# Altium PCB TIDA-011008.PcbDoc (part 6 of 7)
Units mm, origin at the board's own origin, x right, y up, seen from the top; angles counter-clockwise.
Board outline 252 x 205 mm, 4 copper layers (Top Layer, Inner Layer 1, Inner Layer 2, Bottom Layer), stack 1.926 mm thick; 517 components, 293 nets, 1426 pads, 1855 vias.
Unrouted connection lines stored in the file: 4.
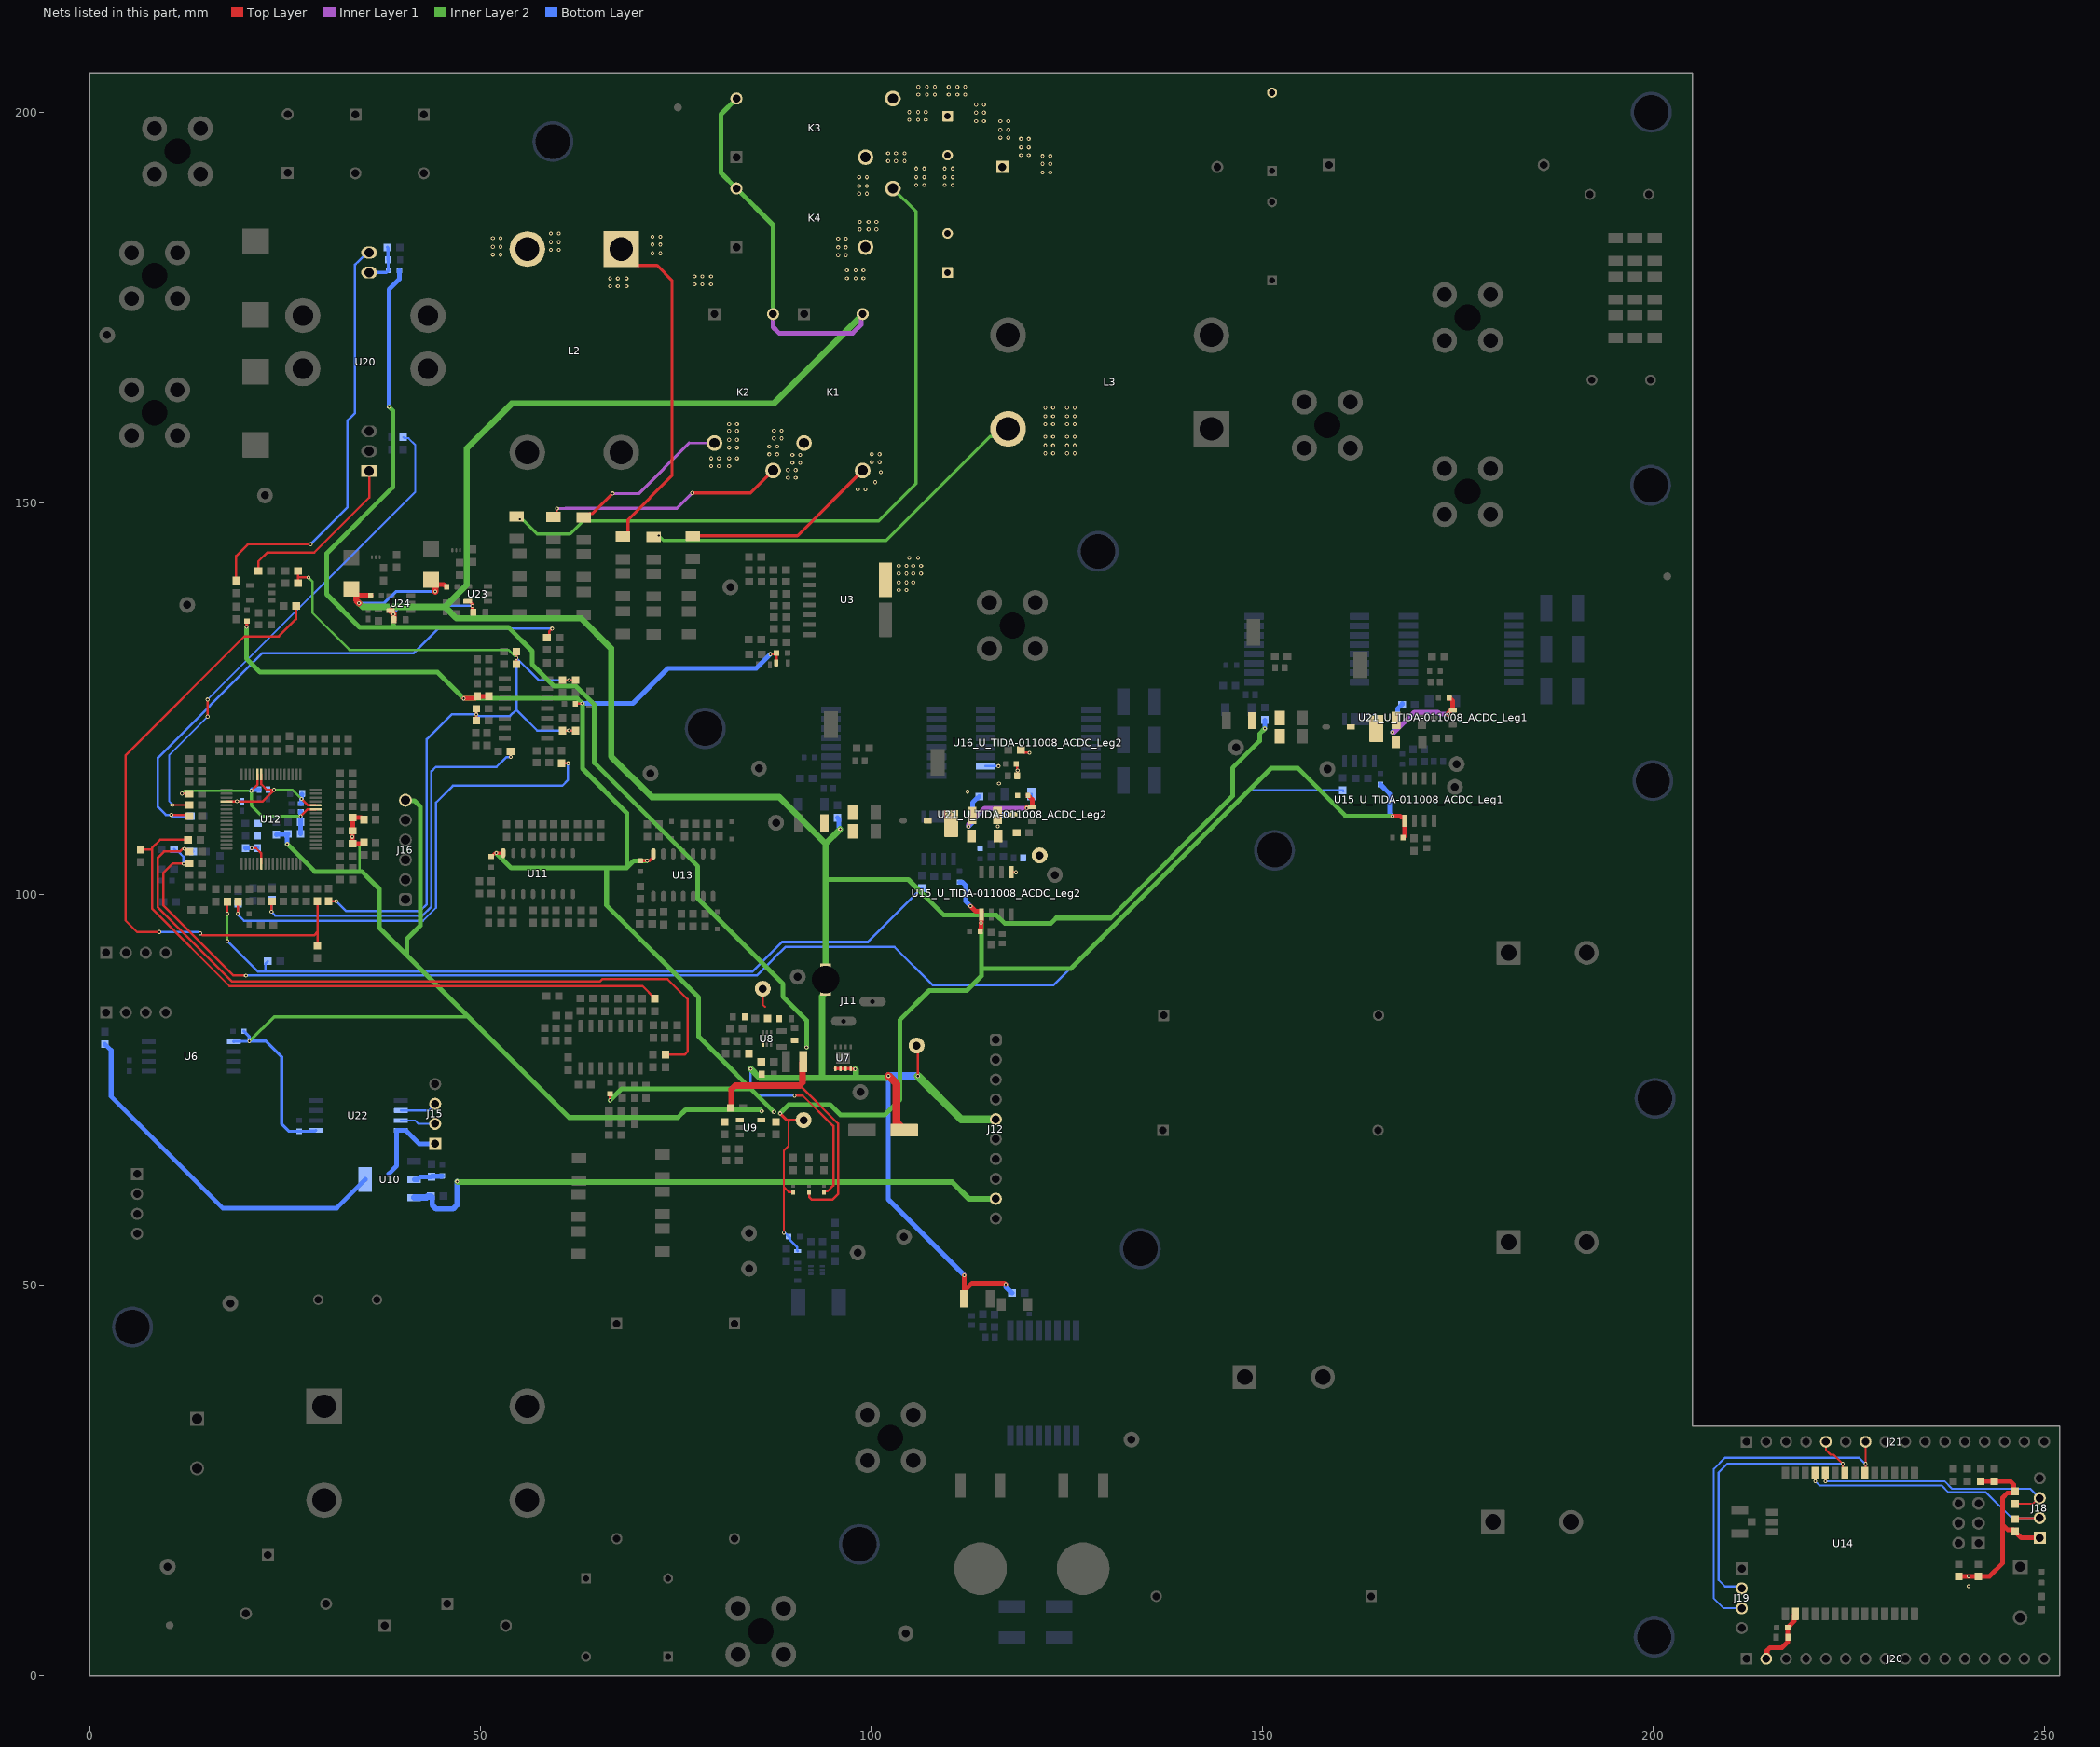
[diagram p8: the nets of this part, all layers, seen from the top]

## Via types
v1: diameter 0.508, hole 0.254, Top Layer to Bottom Layer, tented both sides, 1852 vias
v2: diameter 1.5/1.5/1.5/1.5 (per signal layer), hole 1, Top Layer to Bottom Layer, 2 vias
v3: diameter 0.508, hole 0.254, Top Layer to Bottom Layer, 1 vias

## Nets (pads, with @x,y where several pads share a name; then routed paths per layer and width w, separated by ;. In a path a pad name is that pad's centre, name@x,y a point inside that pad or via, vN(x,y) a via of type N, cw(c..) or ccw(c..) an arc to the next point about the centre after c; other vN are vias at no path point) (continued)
SN_U_TIDA-011008_ACDC_Leg2: C19_U_TIDA-011008_ACDC_Leg2.2 C109_U_TIDA-011008_ACDC_Leg2.1 C110_U_TIDA-011008_ACDC_Leg2.2 C111_U_TIDA-011008_ACDC_Leg2.2 C112_U_TIDA-011008_ACDC_Leg2.2 C113_U_TIDA-011008_ACDC_Leg2.1 C114_U_TIDA-011008_ACDC_Leg2.1 C115_U_TIDA-011008_ACDC_Leg2.1 C117_U_TIDA-011008_ACDC_Leg2.1 D14_U_TIDA-011008_ACDC_Leg2.2 R177_U_TIDA-011008_ACDC_Leg2.1 TP28_U_TIDA-011008_ACDC_Leg2.1 U15_U_TIDA-011008_ACDC_Leg2.5 U16_U_TIDA-011008_ACDC_Leg2.10 U21_U_TIDA-011008_ACDC_Leg2.3 | length 6.3
  Top Layer w0.3: U15_U_TIDA-011008_ACDC_Leg2.5@117.897,102.808 v1(118.495,102.808) v1@118.53,102.773 ; C113_U_TIDA-011008_ACDC_Leg2.1@118.53,116.65 118.664,116.515 118.664,115.847 v1(118.704,115.807) ; C115_U_TIDA-011008_ACDC_Leg2.1@118.642,115.158 118.705,115.221 v1(118.704,115.807) ; R177_U_TIDA-011008_ACDC_Leg2.1@119.115,118.44 119.44,118.115 120.2,118.115 v1@120.238,118.077
  Top Layer w0.8: C111_U_TIDA-011008_ACDC_Leg2.2@116.163,107.608 C111_U_TIDA-011008_ACDC_Leg2.2@116.2,107.571
  Bottom Layer w0.3: U16_U_TIDA-011008_ACDC_Leg2.10@114.605,116.376 116.252,116.376 v1(116.255,116.373) ; C112_U_TIDA-011008_ACDC_Leg2.2@120.493,112.577 C112_U_TIDA-011008_ACDC_Leg2.2@120.493,112.827
  Bottom Layer w0.8: D14_U_TIDA-011008_ACDC_Leg2.2@116.235,110.254 116.235,110.199 116.293,110.141 v1(116.988,110.141)
  other v1: 116.163,108.667 112.288,113.117 116.316,114.155 120.219,118.096
SWCLK: J19.3 J21.7 U14.20 | length 45.1
  Top Layer w0.254: U14.20@227.07,25.975 227.16,26.065 v1(227.16,27.156) J21.7@227.16,29.975
  Bottom Layer w0.254: J19.3@211.32,8.685 209.003,8.685 207.75,9.938 207.75,26.507 209.16,27.917 226.336,27.917 227.098,27.156 v1(227.16,27.156) ; J21.7@227.114,29.929 J21.7@227.16,29.975
SWDIO: J19.2 J21.5 U14.22 | length 38.7
  Top Layer w0.254: J21.5@222.08,29.975 222.08,28.92 222.693,28.307 223.086,28.307 v1(224.237,27.156) 224.237,26.268 U14.22@224.53,25.975
  Bottom Layer w0.254: J19.2@211.32,11.225 211.072,11.473 209.188,11.473 208.357,12.304 208.357,26.052 209.461,27.156 v1(224.237,27.156)
TEMP_SW1: C120_U_TIDA-011008_ACDC_Leg1.1 R135.2 R178_U_TIDA-011008_ACDC_Leg1.1 | length 179.1
  Top Layer w0.3: R135.2@12.79,103.965 12.727,103.902 v1(12.04,103.902) 10.625,103.902 9.426,102.703 9.426,98.569 18.393,89.601 v1(20,89.601)
  Bottom Layer w0.3: C120_U_TIDA-011008_ACDC_Leg1.1@10.824,105.749 11.149,105.424 11.375,105.424 12.001,104.799 12.001,103.942 v1(12.04,103.902) ; v1(20,89.601) 85.371,89.601 87.52,91.75 87.52,91.775 88.995,93.25 102.968,93.25 107.869,88.349 123.266,88.349 148.187,113.27 R178_U_TIDA-011008_ACDC_Leg1.1@160.298,113.27 R178_U_TIDA-011008_ACDC_Leg1.1@160.373,113.195
TEMP_SW2: C120_U_TIDA-011008_ACDC_Leg2.1 R136.2 R178_U_TIDA-011008_ACDC_Leg2.1 | length 101.5
  Top Layer w0.3: v1(17.628,97.5) R136.2@17.628,99.056
  Inner Layer 2 w0.3: v1(17.628,94) v1(17.628,97.5)
  Bottom Layer w0.3: v1(17.628,94) 21.525,90.103 22.472,90.103 ; C120_U_TIDA-011008_ACDC_Leg2.1@22.799,91.421 22.797,91.421 22.472,91.096 22.472,90.103 ; R178_U_TIDA-011008_ACDC_Leg2.1@106.53,100.699 R178_U_TIDA-011008_ACDC_Leg2.1@106.455,100.774 106.455,100.749 106.13,100.424 106.105,100.424 99.564,93.883 88.593,93.883 84.813,90.103 22.472,90.103
UART1_RX: J15.3 J18.3 R167.1 U14.24 U22.6 | length 38
  Top Layer w0.254: U14.24@221.99,25.975 222.042,25.923 v1(222.042,24.926) ; R167.1@245.995,21.75 R167.1@246.285,22.04 248.53,22.04 249.255,22.765 J18.3@249.44,22.765
  Bottom Layer w0.254: U22.6@39.83,72.335 43.357,72.335 J15.3@44.202,73.18 ; v1(222.042,24.926) 237.268,24.926 238.242,23.952 248.253,23.952 J18.3@249.44,22.765
UART1_TX: J15.2 J18.2 R168.1 U14.25 U22.7 | length 39.5
  Top Layer w0.254: v1(220.715,24.931) 220.715,25.97 U14.25@220.72,25.975 ; R168.1@246.285,20.065 R168.1@246.285,20.09 246.42,20.225 J18.2@249.44,20.225
  Bottom Layer w0.254: U22.7@39.83,71.065 41.621,71.065 42.046,70.64 J15.2@44.202,70.64 ; v1(220.715,24.931) 221.255,24.39 236.875,24.39 237.747,23.518 242.543,23.518 245.836,20.225 J18.2@249.44,20.225
V_ZCD: C132.2 R195.2 R200.2 | length 83
  Top Layer w0.3: v1(8.945,95.162) 6.083,95.162 4.59,96.655 4.59,117.749 19.807,132.967 24.2,132.967 26.408,135.175 R195.2@26.408,136.855 ; v1(14.178,94.987) 14.207,94.987 14.454,94.741 28.706,94.741 29.145,95.179 ; C132.2@29.145,93.437 29.145,95.179 ; R200.2@29.145,99.081 29.145,95.179
  Bottom Layer w0.3: v1(8.945,95.162) 13.947,95.162 14.122,94.987 v1(14.178,94.987)
VAC_input: C53.2 R67.2 R138.2 | length 63.9
  Top Layer w0.3: v1(18.967,97.5) 18.967,98.994 R138.2@19.029,99.056 ; R67.2@60.376,116.739 60.383,116.731 v1(61.204,116.731)
  Bottom Layer w0.3: C53.2@19.029,98.824 18.967,98.763 v1(18.967,97.5) 18.967,97.398 19.767,96.599 42.641,96.599 44.311,98.269 44.311,111.714 46.472,113.875 60.466,113.875 61.204,114.614 v1(61.204,116.731)
VAC_L: K2.2 L2.2 R58.1 | length 20.6
  Top Layer w0.4: R58.1@63.221,148.35 63.621,148.35 63.944,148.673 64.325,148.673 v1(66.895,151.243)
  Inner Layer 1 w0.254: 76.691,157.691 K2.2@79.93,157.691
  Inner Layer 1 w0.4: v1(66.895,151.243) 66.913,151.225 68.428,151.225 68.433,151.22 70.22,151.22 76.691,157.691
  other v1: 79.5,154.739 80.495,154.739 81.808,154.739 79.5,155.739 80.495,155.739 81.808,155.739 82.804,155.739 81.808,157.114 82.804,157.114 81.808,158.114 82.804,158.114 81.808,159.25 82.804,159.25 81.808,160.096 82.804,160.096 51.58,181.79 52.576,181.79 59.014,182.392 60.01,182.392 51.58,182.79 52.576,182.79 59.014,183.392 60.01,183.392 51.58,183.898 52.576,183.898 59.014,184.5 60.01,184.5
VAC_L_Relay: K1.2 K2.3 R12.2 R61.1 | length 30.9
  Top Layer w0.254: R61.1@59.34,148.403 59.522,148.403 59.845,148.726 59.793,148.726 v1(59.793,149.327)
  Top Layer w0.4: v1(77.1,151.325) 84.564,151.325 K2.3@87.43,154.191
  Inner Layer 1 w0.4: v1(59.793,149.327) 60.821,149.327 60.847,149.354 75.128,149.354 v1(77.1,151.325)
  other v1: 89.32,153.245 90.316,153.245 89.32,154.245 90.316,154.245 89.897,155.164 90.893,155.164 89.897,156.164 90.893,156.164 86.945,156.256 87.94,156.256 86.945,157.256 87.94,157.256 87.527,158.289 88.522,158.289 87.527,159.289 88.522,159.289
VAC_L_SW: K1.3 R12.1 R64.1 U3.2 | length 25.2
  Top Layer w0.4: R64.1@77.153,145.85 90.541,145.85 K1.3@98.882,154.191
  other v1: 103.5,138.876 104.495,138.876 103.5,139.876 104.495,139.876 105.356,139.876 103.5,141 104.495,141 105.356,141 106.351,141 103.5,142 104.495,142 105.356,142 106.351,142 104.85,143.015 105.974,143.015 98.25,151.754 99.245,151.754 100.503,152.694 101.198,153.975 100.054,155.257 101.049,155.257 100.054,156.257 101.049,156.257
VAC_N: K4.2 L2.1 R70.1 | length 43.6
  Top Layer w0.254: L2.1@68,182.5 L2.1@70.103,180.397 ; R70.1@68.201,145.871 68.551,145.871 R70.1@68.874,146.194
  Top Layer w0.4: R70.1@68.874,146.194 68.874,147.874 74.5,153.5 74.5,178.5 72.603,180.397 L2.1@70.103,180.397
  other v1: 66.568,177.755 67.568,177.755 68.676,177.755 77.381,178.006 78.381,178.006 79.489,178.006 66.568,178.75 67.568,178.75 68.676,178.75 96.875,178.773 97.983,178.773 98.983,178.773 77.381,179.002 78.381,179.002 79.489,179.002 96.875,179.768 97.983,179.768 98.983,179.768 95.75,181.718 96.745,181.718 72.005,181.97 73,181.97 95.75,182.718 96.745,182.718 72.005,183.078 73,183.078 95.75,183.826 96.745,183.826 72.005,184.078 73,184.078 98.533,184.99 99.641,184.99 100.641,184.99 98.533,185.985 99.641,185.985 100.641,185.985
VAC_N_Relay: K3.2 K4.3 R25.2 R73.1 | length 93.8
  Top Layer w0.4: R73.1@54.595,148.477 54.719,148.477 55.042,148.154 v1(55.042,147.941)
  Inner Layer 2 w0.4: v1(55.042,147.941) 55.373,147.941 57.241,146.073 61.457,146.073 62.912,147.529 63.142,147.758 100.934,147.758 105.694,152.519 105.694,187.306 K4.3@102.75,190.25
  other v1: 98.429,189.58 99.425,189.58 98.429,190.58 99.425,190.58 105.75,190.688 106.745,190.688 109.386,190.688 110.381,190.688 98.429,191.688 99.425,191.688 105.75,191.688 106.745,191.688 109.386,191.688 110.381,191.688 105.75,192.796 106.745,192.796 109.386,192.796 110.381,192.796 102.142,193.755 103.142,193.755 104.25,193.755 102.142,194.75 103.142,194.75 104.25,194.75
VAC_N_SW: C27.1 C30.2 K3.3 L3.4 R25.1 R76.1 | length 51.5
  Top Layer w0.4: R76.1@72.136,145.843 v1(72.806,145.843)
  Inner Layer 2 w0.4: v1(72.806,145.843) 72.822,145.843 73.415,145.25 101.906,145.25 115.195,158.539 115.416,158.539 116.377,159.5 L3.4@117.5,159.5
  other v1: 122.25,156.387 123.245,156.387 125.017,156.387 126.012,156.387 122.25,157.387 123.245,157.387 125.017,157.387 126.012,157.387 122.25,158.495 123.245,158.495 125.017,158.495 126.012,158.495 122.25,160.123 123.245,160.123 125.017,160.123 126.012,160.123 122.25,161.123 123.245,161.123 125.017,161.123 126.012,161.123 122.25,162.231 123.245,162.231 125.017,162.231 126.012,162.231 121.882,192.292 122.878,192.292 121.882,193.401 122.878,193.401 121.882,194.401 122.878,194.401 119.13,194.5 120.125,194.5 119.13,195.5 120.125,195.5 119.13,196.608 120.125,196.608 116.505,196.75 117.5,196.75 116.505,197.75 117.5,197.75 113.405,198.858 114.4,198.858 116.505,198.858 117.5,198.858 104.855,199.031 105.963,199.031 106.963,199.031 113.405,199.966 114.4,199.966 104.855,200.026 105.963,200.026 106.963,200.026 113.405,200.966 114.4,200.966 106.006,202.25 107.114,202.25 108.114,202.25 109.892,202.25 111,202.25 112,202.25 106.006,203.245 107.114,203.245 108.114,203.245 109.892,203.245 111,203.245 112,203.245
VAC_relay: C54.2 R68.2 R148.2 | length 72.1
  Top Layer w0.3: v1(10.45,110.14) 12.615,110.14 R148.2@12.79,109.965 ; R68.2@58.495,132.827 58.768,133.1 58.768,133.565 v1(59.162,133.959)
  Bottom Layer w0.3: C54.2@12.974,109.965 10.681,109.965 10.506,110.14 v1(10.45,110.14) 9.758,110.14 8.75,111.148 8.75,117.447 22.125,130.823 41.454,130.823 44.625,133.993 59.128,133.993 v1(59.162,133.959)
VAC_sw: C55.2 R69.2 R139.2 | length 53
  Top Layer w0.3: v1(23.265,97.75) 23.265,98.989 R139.2@23.348,99.072 ; R69.2@53.868,118.263 53.868,117.55 v1@53.88,117.538
  Bottom Layer w0.3: C55.2@23.348,99.299 23.265,99.216 v1(23.265,97.75) 23.761,97.254 42.56,97.254 43.733,98.427 43.733,115.707 44.289,116.264 52.043,116.264 53.318,117.538 v1(53.868,117.538)
VCC_1V2: C92.2 C93.2 C94.2 C95.2 U12.4 U12.44 U12.59 | length 18.8
  Top Layer w0.3: U12.4@17.515,111.852 18.829,111.852 v1(18.849,111.872) 18.878,111.843 22.103,111.843 v1(23.6,113.34) 22.687,113.34 21.965,114.062 U12.59@21.965,115.302 ; v1(27.115,112.177) 27.94,111.352 U12.44@28.915,111.352
  Inner Layer 2 w0.3: v1(23.6,113.34) 23.634,113.375 25.918,113.375 v1(27.115,112.177)
  Bottom Layer w0.3: v1(18.849,111.872) 18.852,111.875 19.501,111.875 C93.2@19.504,111.877 ; C92.2@22.84,113.377 22.859,113.359 23.582,113.359 v1(23.6,113.34)
  Bottom Layer w0.6: C94.2@27.015,111.577 27.115,111.577 v1(27.115,112.177) 27.115,112.702 C95.2@27.19,112.777
VCC_1V65: C48.2 C50.2 C51.2 C52.2 C131.2 R49.2 R55.2 R56.2 R57.2 R197.1 R202.2 | length 112.1
  Top Layer w0.3: 26.665,140.282 26.665,140.5 ; C131.2@26.665,141.307 26.665,140.532 26.697,140.5 v1(28,140.5) ; R202.2@30.593,99.097 30.596,99.094 v1(31.563,99.094) ; R57.2@49.467,122.192 v1(49.467,122.992) C52.2@49.467,123.717 ; R49.2@54.593,129.397 v1(54.593,130.22) C48.2@54.593,131.043 ; R55.2@60.476,120.94 v1(61.308,120.94) 62.141,120.94 C50.2@62.154,120.926 ; R56.2@60.476,127.38 v1(61.315,127.38) C51.2@62.154,127.38
  Inner Layer 2 w0.3: v1(28,140.5) 28.5,140 28.5,136 33.25,131.25 53.563,131.25 v1(54.593,130.22)
  Bottom Layer w0.3: v1(31.563,99.094) 32.801,97.857 42.271,97.857 43.136,98.721 43.136,119.819 46.308,122.992 49.52,122.992 49.743,122.77 53.77,122.77 54.593,123.593 ; v1(61.308,120.94) 57.246,120.94 54.593,123.593 ; v1(61.315,127.38) 57.433,127.38 v1(54.593,130.22) 54.593,123.593
VCC_3V3: C43.2 C65.1 C67.1 C72.2 C84.2 C89.2 C97.1 C103.1 C108_U_TIDA-011008_ACDC_Leg1.2 C108_U_TIDA-011008_ACDC_Leg2.2 D8.2 FB1.1 FB4.1 FB5.2 FB6.1 FB7_U_TIDA-011008_ACDC_Leg1.1 FB7_U_TIDA-011008_ACDC_Leg2.1 FB8.1 J16.6 L7.1 L8.1 R9.2 R35.2 R38.1 R155.2 R156.2 R157.2 R190.2 R191.2 TP20.1 U6.1 U9.5 U11.16 U13.14 U15_U_TIDA-011008_ACDC_Leg1.1 U15_U_TIDA-011008_ACDC_Leg2.1 U22.1 | length 508.1
  Top Layer w0.254: v1(88.8,56.717) 88.8,62.54 ; 89.6,71.108 89.425,70.933 89.425,67.84 88.8,67.215 88.8,62.54 ; D8.2@90.012,61.9 89.44,61.9 88.8,62.54
  Top Layer w0.3: FB6.1@62.127,124.332 62.165,124.37 62.978,124.37 v1(63.016,124.407) ; v1(87.081,130.685) 87.7,130.685 FB4.1@87.87,130.855 87.87,129.635 R35.2@87.82,129.585
  Top Layer w0.4: v1(20.083,134.171) 20.104,134.192 20.104,134.895 FB8.1@20.132,134.923 ; C84.2@51.368,104.81 51.393,104.81 51.568,104.985 51.568,105.01 51.818,105.26 v1(52.021,105.26) U11.16@52.923,105.26 ; v1(66.579,73.64) FB5.2@66.579,74.477 ; C89.2@70.432,104.281 v1(71.307,104.281) 71.618,104.281 72.122,104.785 U13.14@72.122,105.156 ; v1(88.325,71.968) 89.184,71.108 89.6,71.108 TP20.1@91.33,71.108
  Top Layer w0.6: R191.2@35.088,106.577 34.938,106.577 34.823,106.462 R157.2@33.647,106.462 33.624,106.484 v1(33.624,107.337) 33.624,108.068 R155.2@33.659,108.102 33.652,108.109 33.652,109.801 R156.2@33.645,109.808 34.732,109.808 34.938,109.602 R190.2@35.088,109.602 ; v1(47.856,125.034) C43.2@49.318,125.034 ; C43.2@49.598,125.314 R38.1@51.098,125.314 ; v1(112.68,98.471) 113.356,97.795 114.087,97.795 U15_U_TIDA-011008_ACDC_Leg2.1@114.087,97.408 114.087,96.382 v1(114.031,96.325) 114.031,95.676 113.942,95.588 113.942,95.258 C108_U_TIDA-011008_ACDC_Leg2.2@113.917,95.233 ; v1(166.662,109.976) 167.61,109.976 167.707,109.879 168.182,109.879 U15_U_TIDA-011008_ACDC_Leg1.1@168.182,109.404 168.182,107.424 168.012,107.254 C108_U_TIDA-011008_ACDC_Leg1.2@168.012,107.229
  Inner Layer 2 w0.3: v1(33.624,107.337) 33.658,107.303 33.658,106.981 34.517,106.123 34.517,102.899
  Inner Layer 2 w0.4: v1(20.438,81.212) 20.467,81.212 20.521,81.266 20.532,81.266 23.6,84.334 48.439,84.334
  Inner Layer 2 w0.6: v1(20.083,134.171) 20.083,130.111 21.818,128.376 44.514,128.376 v1(47.856,125.034) 62.389,125.034 v1(63.016,124.407) ; v1(25.286,106.418) 28.804,102.899 34.517,102.899 34.82,102.899 35.863,101.856 35.881,101.856 37.063,100.673 37.063,95.709 40.595,92.177 ; J16.6@40.399,112.017 40.482,111.934 41.556,111.934 42.306,111.184 42.306,95.982 40.595,94.272 40.595,92.177 ; v1(52.021,105.26) 53.916,103.364 66.128,103.364 ; v1@63.048,124.375 63.048,116.049 68.702,110.395 68.702,103.364 ; v1(66.579,73.64) 68.04,75.101 84.344,75.101 ; v1@71.303,104.276 69.614,104.276 68.702,103.364 ; v1(85.966,72.257) 85.81,72.413 76.229,72.413 75.258,71.442 61.33,71.442 48.439,84.334 40.595,92.177 ; v1(87.537,72.161) 77.915,81.784 77.915,86.783 66.128,98.569 66.128,103.364 ; v1(88.325,71.968) 89.425,73.068 94.728,73.068 96.039,71.757 101.701,71.757 103.676,73.732 103.676,83.948 107.412,87.684 112.208,87.684 114.087,89.563 114.087,90.5 ; v1(114.031,96.325) 114.087,96.269 114.087,90.5 ; v1@166.636,110.002 160.661,110.002 154.528,116.135 151.167,116.135 125.532,90.5 114.087,90.5 ; 66.128,103.364 68.702,103.364
  Bottom Layer w0.3: v1(88.8,56.717) 88.924,56.717 FB1.1@89.425,56.215 89.625,56.015 89.625,55.743 90.485,54.883 90.485,54.448 R9.2@90.575,54.359
  Bottom Layer w0.4: U6.1@18.46,81.155 18.497,81.191 20.417,81.191 v1(20.438,81.212) ; C65.1@19.748,82.475 20.417,81.805 20.417,81.233 v1(20.438,81.212) ; U22.1@28.93,69.795 28.83,69.695 28.23,69.695 28.214,69.679 C67.1@26.822,69.679 25.505,69.679 24.575,70.61 24.575,79.174 22.536,81.212 v1(20.438,81.212)
  Bottom Layer w0.6: C103.1@23.895,107.615 23.933,107.653 L8.1@25.353,107.653 ; v1(25.286,106.418) 25.286,107.586 L8.1@25.353,107.653 ; L8.1@25.39,107.69 L8.1@25.353,107.653 ; v1(63.016,124.407) 63.024,124.399 69.504,124.399 73.972,128.866 85.261,128.866 v1(87.081,130.685) ; FB7_U_TIDA-011008_ACDC_Leg2.1@111.26,101.54 111.31,101.49 111.702,101.49 112.054,101.139 112.054,99.097 v1(112.68,98.471) ; FB7_U_TIDA-011008_ACDC_Leg1.1@165.104,114.036 166.275,112.865 166.275,110.363 v1(166.662,109.976)
VCC_3V3_Wifi: C68.2 C74.2 C105.2 C106.2 J15.1 J18.1 J20.2 L6.1 R162.2 R163.2 R167.2 R168.2 R169.2 R170.2 U10.2 U10.4 U14.2 U22.8 | length 97.9
  Top Layer w0.6: J20.2@214.46,2.225 214.557,2.322 214.557,3.261 214.929,3.633 216.462,3.633 217.2,4.371 217.2,4.925 C105.2@217.275,5 217.2,5.075 C106.2@217.2,6.207 218.03,7.037 218.03,7.825 U14.2@218.112,7.908 ; R163.2@239.085,12.75 R162.2@241.605,12.75 243.005,12.75 244.702,14.447 244.702,19.355 ; R169.2@241.865,24.918 245.675,24.918 246.11,24.483 246.11,23.815 R167.2@246.285,23.64 246.285,23.615 246.11,23.44 245.313,23.44 244.702,22.829 244.702,19.355 ; R168.2@246.285,18.465 247.065,17.685 J18.1@249.44,17.685 ; R168.2@246.285,18.49 246.285,18.515 246.11,18.69 245.367,18.69 244.702,19.355
  Bottom Layer w0.6: L6.1@1.961,80.831 1.961,80.806 2.136,80.631 2.161,80.631 2.761,80.031 2.761,74.126 17.017,59.87 31.617,59.87 U10.4@35.262,63.514 ; 38.275,64.245 39.29,65.26 39.29,69.795 40.43,69.795 42.125,68.1 J15.1@44.202,68.1 ; U10.2@41.512,63.514 41.937,63.514 42.281,63.858 C74.2@43.727,63.858 43.8,63.931 45.063,63.931 C68.2@45.113,63.981
  other v1: 240.345,11.512 240.345,12.75
VCC_5V: C71.2 C76.1 C79.1 C80.1 C138.2 C139.2 D7.2 FB9.2 L5.2 R101.2 R103.2 TP22.1 U9.1 U23.5 U24.5 | length 195.4
  Top Layer w0.254: TP22.1@86.108,87.915 86.108,85.876 86.39,85.594
  Top Layer w0.3: 90.877,75.518 95.726,70.669 95.726,61.657 95.005,60.936 92.405,60.936 92.041,61.301 92.041,61.892 D7.2@92.033,61.9
  Top Layer w0.4: U23.5@48.365,137.443 48.615,137.443 48.959,137.098 v1(48.959,136.876) 48.959,136.183 C139.2@49.095,136.048
  Top Layer w0.8: U24.5@38.501,136.252 38.551,136.252 38.876,135.926 v1(38.876,135.776) 38.876,135.088 C138.2@38.874,135.086 ; C71.2@82.008,72.658 82.033,72.658 82.108,72.733 82.108,73.168 82.109,73.169 82.109,75.049 82.578,75.518 90.877,75.518 ; 90.837,75.558 91.187,75.907 91.187,78.512 L5.2@91.283,78.608
  Inner Layer 2 w0.6: v1(38.298,162.329) 38.773,161.854 38.773,152.023 30.324,143.574 30.324,138.349 34.55,134.123 39.146,134.123 ; 38.876,134.104 39.164,134.104 ; v1(38.876,135.776) 38.876,134.392 39.164,134.104 ; v3(91.708,80.409) 91.708,83.866 88.682,86.891 88.682,88.537 77.799,99.421 77.799,103.559 64.569,116.79 64.569,124.247 62.223,126.593 59.421,126.593 56.63,129.385 56.63,131.071 53.596,134.104 39.164,134.104
  Bottom Layer w0.3: v1(38.876,135.776) 38.916,135.815 38.916,135.992 39.801,136.876 v1(48.959,136.876)
  Bottom Layer w0.6: v1(38.298,162.329) 38.298,177.344 39.623,178.669 FB9.2@39.623,179.756
VCC_5V_WiFi: C73.2 J12.9 U10.3 | length 79.9
  Inner Layer 2 w0.7: v1(47.003,63.264) 47.085,63.182 110.318,63.182 112.448,61.052 J12.9@115.917,61.052
  Bottom Layer w0.7: C73.2@43.602,61.333 43.777,61.333 43.827,61.283 43.827,60.247 44.324,59.75 46.5,59.75 47.003,60.253 v1(47.003,63.264)
  Bottom Layer w0.8: U10.3@41.512,61.214 41.525,61.228 43.108,61.228 43.213,61.333 C73.2@43.602,61.333
VCC_12V: C9.1 C28.2 C29.2 C69.1 C75.1 C77.2 C123_U_TIDA-011008_ACDC_Leg1.1 C123_U_TIDA-011008_ACDC_Leg2.1 D2.1 D3.1 D6.2 J11.1 J12.5 K1.4 K2.4 K3.4 K4.4 R1.1 R102.2 R171_U_TIDA-011008_ACDC_Leg1.1 R171_U_TIDA-011008_ACDC_Leg2.1 R172_U_TIDA-011008_ACDC_Leg1.1 R172_U_TIDA-011008_ACDC_Leg2.1 R179_U_TIDA-011008_ACDC_Leg1.1 R179_U_TIDA-011008_ACDC_Leg2.1 TP7.1 U7.1 U7.2 U7.3 U7.4 U8.1 | length 445.9
  Top Layer w0.3: v1(90.183,74.243) 91.226,74.243 95.131,70.338 95.131,62.761 94.382,62.012 94.033,62.012 93.933,61.912 D6.2@93.933,61.9 ; TP7.1@105.793,80.646 105.951,80.488 v1(105.951,76.743)
  Top Layer w0.4: U7.1@95.408,77.679 U7.2@96.058,77.679 U7.3@96.708,77.679 U7.4@97.358,77.679 97.399,77.638 v1(97.908,77.638)
  Top Layer w0.6: D3.1@34.1,138.425 34.322,138.203 C28.2@35.97,138.203 ; D2.1@44.588,139.62 45.289,139.62 45.552,139.356 45.64,139.356 45.665,139.331 C29.2@45.665,139.306 ; C9.1@111.875,48.275 112,48.4 112,49.374 112.892,50.266 117.027,50.266 v1(117.191,50.101) ; C9.1@111.875,48.825 v1(111.875,51.262)
  Top Layer w0.8: D3.1@33.5,139.025 34.1,138.425 34.1,137.592 v1(34.467,137.226) ; D2.1@43.694,140.193 44.214,139.673 v1(44.214,138.704)
  Top Layer w1: v1(102.199,76.761) 103.211,75.749 103.211,70.803 ; C69.1@103.211,70.112 103.211,70.803 ; C69.1@103.511,69.812 C69.1@104.201,69.812 103.211,70.803
  Inner Layer 1 w0.6: K2.4@87.43,174.191 87.434,174.188 87.434,172.516 88.2,171.75 97.612,171.75 98.7,172.838 98.7,174.01 K1.4@98.882,174.191
  Inner Layer 2 w0.6: K3.4@82.75,201.75 80.75,199.75 80.75,192.25 K4.4@82.75,190.25 87.43,185.57 K2.4@87.43,174.191 ; 94.149,101.876 104.721,101.876 109.27,97.328 116.002,97.328 117.037,96.293 122.981,96.293 123.64,96.952 130.612,96.952 146.193,112.533 146.193,116.141 149.646,119.594 149.646,120.507 v1(150.317,121.178)
  Inner Layer 2 w0.8: v1(34.467,137.226) 34.948,136.744 45.463,136.744 ; v1(84.558,77.681) 85.742,76.497 93.829,76.497 ; v1(96,108.321) 94.149,106.469 ; v1(97.908,77.638) 98.033,77.513 98.033,76.497 ; K1.4@98.882,174.127 87.505,162.75 54,162.75 48.25,157 48.25,139.531 45.463,136.744 ; v1@102.164,76.743 101.917,76.497 98.033,76.497 ; 45.463,136.744 46.923,135.284 62.877,135.284 66.716,131.445 66.716,117.622 71.925,112.413 88.205,112.413 94.149,106.469 ; 93.829,76.497 98.033,76.497 ; 93.829,76.497 93.699,76.627 93.699,86.947 93.849,87.097 93.849,88.765 J11.1@94.149,89.065 94.149,101.876 94.149,106.469
  Inner Layer 2 w1: v1(105.951,76.743) 111.481,71.212 J12.5@115.917,71.212
  Bottom Layer w0.3: v1(84.558,77.681) 84.558,75.141 85.456,74.243 v1(90.183,74.243)
  Bottom Layer w0.4: v1(34.467,137.226) 37.718,137.226 39.197,138.704 v1(44.214,138.704)
  Bottom Layer w0.6: R179_U_TIDA-011008_ACDC_Leg2.1@95.648,109.79 95.823,109.615 95.823,108.498 v1(96,108.321) ; v1@102.164,76.743 102.164,60.974 v1(111.875,51.262) ; v1(117.191,50.101) 117.191,49.774 117.965,49 R1.1@117.99,49 ; v1(150.317,121.178) R179_U_TIDA-011008_ACDC_Leg1.1@150.317,122.273
  Bottom Layer w1: v1@102.164,76.743 v1(105.951,76.743)
VCC_12V_SN_U_TIDA-011008_ACDC_Leg1: C110_U_TIDA-011008_ACDC_Leg1.1 C111_U_TIDA-011008_ACDC_Leg1.1 C117_U_TIDA-011008_ACDC_Leg1.2 D13_U_TIDA-011008_ACDC_Leg1.1 D14_U_TIDA-011008_ACDC_Leg1.1 R173_U_TIDA-011008_ACDC_Leg1.1 TP15_U_TIDA-011008_ACDC_Leg1.1 U21_U_TIDA-011008_ACDC_Leg1.2 | length 15.2
  Top Layer w0.6: v1(173.775,123.03) 173.775,123.139 174.167,123.531 U21_U_TIDA-011008_ACDC_Leg1.2@174.367,123.531 174.367,124.723 174.015,125.075 173.921,125.075 173.896,125.1 C117_U_TIDA-011008_ACDC_Leg1.2@173.896,125.125
  Inner Layer 1 w0.6: v1(166.662,120.699) 166.886,120.699 169.468,123.281 172.467,123.281 172.718,123.03 v1(173.775,123.03)
  Bottom Layer w0.6: v1(166.662,120.699) 167.142,121.178 167.142,122.246 D14_U_TIDA-011008_ACDC_Leg1.1@167.3,122.404 167.3,123.723 167.651,124.074 167.678,124.074 167.891,124.287 R173_U_TIDA-011008_ACDC_Leg1.1@167.891,124.392
VCC_12V_SN_U_TIDA-011008_ACDC_Leg2: C110_U_TIDA-011008_ACDC_Leg2.1 C111_U_TIDA-011008_ACDC_Leg2.1 C117_U_TIDA-011008_ACDC_Leg2.2 D13_U_TIDA-011008_ACDC_Leg2.1 D14_U_TIDA-011008_ACDC_Leg2.1 R173_U_TIDA-011008_ACDC_Leg2.1 TP15_U_TIDA-011008_ACDC_Leg2.1 U21_U_TIDA-011008_ACDC_Leg2.2 | length 15.5
  Top Layer w0.6: v1(119.867,111.006) 120.026,111.165 U21_U_TIDA-011008_ACDC_Leg2.2@120.567,111.165 120.567,112.108 120.092,112.583 120.067,112.583 120.042,112.608 C117_U_TIDA-011008_ACDC_Leg2.2@120.042,112.633
  Inner Layer 1 w0.6: v1(112.413,108.641) 112.413,108.911 114.508,111.006 v1(119.867,111.006)
  Bottom Layer w0.6: v1(112.413,108.641) 112.803,109.031 112.803,110.097 D14_U_TIDA-011008_ACDC_Leg2.1@112.96,110.254 112.96,111.725 113.552,112.317 113.624,112.317 R173_U_TIDA-011008_ACDC_Leg2.1@113.799,112.492
VCC_ZCD: C135.1 C136.2 FB9.1 U20.4 | length 5.6
  Bottom Layer w0.4: U20.4@35.762,179.5 37.966,179.5 FB9.1@38.223,179.756 38.195,179.785 38.195,181.082 C135.1@38.167,181.11 38.167,182.64 C136.2@38.092,182.715
VCCA_3V3: C98.1 L7.2 U12.22 | length 4.4
  Top Layer w0.3: v1@20.684,105.861 v1(20.723,105.899) 21.29,105.899 21.965,105.224 U12.22@21.965,103.902
  Bottom Layer w0.6: C98.1@19.965,105.877 19.987,105.899 v1(20.723,105.899) 21.462,105.899 L7.2@21.465,105.902
VCCIO_3V3: C99.1 C100.1 C104.1 L8.2 R158.2 U12.43 U12.60 | length 27.3
  Top Layer w0.3: v1(11.829,112.875) 12.78,112.875 R158.2@12.79,112.865 ; v1(20.696,113.223) 21.465,113.993 U12.60@21.465,115.302 ; v1(27.005,109.954) 27.904,110.852 U12.43@28.915,110.852
  Inner Layer 2 w0.3: v1(11.829,112.875) 12.177,113.223 v1(20.696,113.223)
  Inner Layer 2 w0.4: v1(20.696,113.223) 20.696,111.341 22.083,109.954 v1(27.005,109.954)
  Bottom Layer w0.6: v1(20.696,113.223) 20.822,113.349 C100.1@21.665,113.349 ; L8.2@26.99,107.69 C104.1@26.99,109.19 27.005,109.205 v1(27.005,109.954) 27.005,110.552 C99.1@27.015,110.552
VDC_sense: C44.1 R42.2 R140.2 | length 94.8
  Top Layer w0.3: R140.2@12.79,105.465 12.465,105.79 12.136,105.79 v1(12.133,105.793) 12.094,105.754 11.862,105.754 11.574,105.465 9.52,105.465 8.75,104.696 8.75,98.308 18.194,88.864 65.312,88.864 65.58,89.132 73.94,89.132 76.5,86.572 76.5,79.866 76.102,79.468 74.64,79.468 R42.2@73.654,79.468
  Bottom Layer w0.3: v1(12.133,105.793) 12.74,105.793 12.743,105.79 12.94,105.79 C44.1@13.265,105.465
Vout_ZCD: R196.2 U20.1 | length 22.2
  Top Layer w0.3: R196.2@21.6,141.35 21.6,142.564 22.75,143.714 28.755,143.714 35.762,150.72 U20.1@35.762,154.12
VPV_sense: C62.2 R87.2 R141.2 | length 83.4
  Top Layer w0.3: C62.2@6.545,105.712 8.028,105.712 8.033,105.708 ; R141.2@12.579,106.959 9.017,106.959 8.033,105.974 8.033,105.708 ; R87.2@72.318,86.64 72.318,86.665 70.734,88.25 17.906,88.25 8.033,98.124 8.033,105.708
Vref_ZCD: R194.2 U20.5 | length 53.8
  Top Layer w0.3: R194.2@18.747,140.1 18.747,143.247 20.25,144.75 v1(28.269,144.75)
  Bottom Layer w0.3: v1(28.269,144.75) 33,149.481 33,160.603 33.959,161.562 33.959,180.506 34.297,180.844 34.31,180.844 35.507,182.04 U20.5@35.762,182.04
ZCD_CHK: R199.2 R201.1 | length 63.4
  Top Layer w0.254: v1(10.586,111.418) 12.777,111.418 R199.2@12.793,111.434 ; v1(15.102,122.701) v1(15.102,124.901)
  Bottom Layer w0.254: v1(10.586,111.418) 10.586,111.487 10.203,111.87 10.203,117.803 v1(15.102,122.701) ; v1(15.102,124.901) 41.655,151.454 41.655,157.459 40.811,158.303 40.257,158.303 R201.1@40.104,158.456
pads on no net: FID1.1 FID2.1 FID3.1 J1. J2. J4. J5. J6. J7. J8. J9. J10. J12.2 J12.3 J12.7 J12.8 J14.1 J14.2 J14.3 J14.4 J20.15 J23.2@211.07,18.225 J23.3@211.07,21.225 LBL1.0 MP1. MP2. MP3. MP4. MP5. MP6. MP6.1 MP7. MP7.1 MP8. MP8.1 MP9. MP9.1 MP10. MP10.1 MP11. MP11.1 MP12. MP12.1 Q1.1@47.423,143.989 Q1.2@46.898,143.989 Q1.3@46.373,143.989 Q2.1@37.139,143.095 Q2.2@36.614,143.095 Q2.3@36.089,143.095 U3.10 U9.4 U12.10 U12.11 U12.29 U12.41 U12.42 U12.55 U17_U_TIDA-011008_ACDC_Leg1.2 U17_U_TIDA-011008_ACDC_Leg2.2

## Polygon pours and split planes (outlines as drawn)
DC_Bus- on Top Layer "TOP_LAYER_DC_BUS-_P261" (solid, remove dead copper, pour order 261): 77 vertices, not listed, extent 1,41.201 174.046,146.75
GND_WiFi on Top Layer "TOP_LAYER_GND_WIFI_P152" (solid, remove dead copper, pour order 152): 207.121,29.975 208.646,31.5 250.25,31.5 251.25,30.5 251.5,30.5 251.5,1.75 250.25,0.5 208.409,0.5 207.192,1.717 207.192,29.905
DC_Bus+ on Top Layer "Top Layer-DC_Bus+" (solid, pour order 265): 53 vertices, not listed, extent 106.315,2.5 203,144.956
DC_Bus- on Top Layer "TOP_LAYER_DC_BUS-_P189" (solid, pour order 189): 18 vertices, not listed, extent 23.413,146.42 45.594,184.75
Relay_Safe on Top Layer "TOP_LAYER_RELAY_SAFE_P082" (solid, pour order 82): 36.388,144.075 36.75,143.714 36.75,141.799 36.52,141.568 32.414,141.568 32.288,141.694 32.288,144.075
Relay_Precharge on Top Layer "TOP_LAYER_RELAY_PRECHARGE_P079" (solid, pour order 79): 42.694,142.687 46.876,142.687 46.876,144.887 46.926,144.937 46.531,145.332 42.783,145.332 42.694,145.243 42.694,142.693
NetD1_3 on Top Layer "TOP_LAYER_NETD1_3_P033" (solid, pour order 33): 19 vertices, not listed, extent 97.317,22.5 127.319,35.805
DC_Bus- on Top Layer "TOP_LAYER_DC_BUS-_P258" (solid, pour order 258): 190.879,141.767 191.389,142.277 197.339,142.277 203,136.615 203,120.454 199.894,117.348 191.585,117.348 190.879,118.054
NetC8_2 on Top Layer "TOP_LAYER_NETC8_2_P238" (solid, pour order 238): 18 vertices, not listed, extent 52.994,0.25 91.421,25.261
NetC12_1 on Top Layer "TOP_LAYER_NETC12_1_P021" (solid, pour order 21): 51.75,28.5 85.85,28.5 91.618,34.268 91.618,49.246 91.328,49.536 88.041,49.536 85.402,46.897 53.892,46.897 50.083,43.088 50.083,30.167
NetL2_3 on Top Layer "TOP_LAYER_NETL2_3_P237" (solid, pour order 237): 43.687,179 48.5,179 51.625,175.875 51.625,172.516 50.517,171.408 42.574,171.408 40.959,173.023 40.959,176.271
VCC_5V on Top Layer "TOP_LAYER_VCC_5V_P120" (solid, pour order 120): 17 vertices, not listed, extent 86.243,80.467 92.26,86.13
SN_U_TIDA-011008_ACDC_Leg1 on Top Layer "TOP_LAYER_SN_U_TIDA-011008_ACDC_LEG1_P223" (solid, pour order 223): 170.056,118.568 170.862,118.568 171.725,119.431 172.571,119.431 172.571,123.399 173.22,124.049 173.22,127.771 172.571,128.421 172.413,128.421 172.413,126.512 169.683,123.782 169.683,118.909 170.056,118.536
SN_U_TIDA-011008_ACDC_Leg2 on Top Layer "TOP_LAYER_SN_U_TIDA-011008_ACDC_LEG2_P222" (solid, pour order 222): 116.015,106.797 116.821,106.797 117.411,107.387 118.642,107.387 118.642,111.74 119.179,112.278 119.179,116 118.53,116.65 118.285,116.65 118.2,116.564 118.2,114.569 115.642,112.011 115.642,107.138 116.015,106.764
AC_L on Top Layer "TOP_LAYER_AC_L_P101" (solid, pour order 101): 7.361,171.739 15,171.739 17,173.739 17,177.975 19.25,180.225 23.591,180.225 24.828,181.463 24.828,185.822 23.75,186.9 6.15,186.9 3.212,183.962 3.212,175.888
DC_Bus- on Top Layer "TOP_LAYER_DC_BUS-_P219" (solid, pour order 219): 95.074,49.481 102.233,49.481 107.223,44.491 107.223,39.458 106.015,38.25 96.245,38.25 95.005,39.489 95.005,49.407 95.074,49.477
PV_Input- on Top Layer "TOP_LAYER_PV_INPUT-_P009" (solid, pour order 9): 25 vertices, not listed, extent 21.25,7 49,39.5
NetC24_1 on Top Layer "TOP_LAYER_NETC24_1_P055" (solid, pour order 55): 101,137.269 104.28,137.269 107.25,140.239 107.25,168.25 115.25,176.25 120.125,176.25 121.25,175.125 121.25,168 119.75,166.5 115.091,166.5 113.591,165 113.591,139.814 106.7,132.923 101,132.923
NetF2_1 on Top Layer "TOP_LAYER_NETF2_1_P093" (solid, pour order 93): 20.375,169.5 29.45,169.5 30.25,168.7 30.25,164.5 29.75,164 19.907,164 19,164.907 19,168.125
NetC25_2 on Top Layer "TOP_LAYER_NETC25_2_P194" (solid, pour order 194): 174.45,186.2 183.5,195.25 187.75,195.25 189.75,193.25 192,193.25 193.99,191.26 193.99,187.99 193.25,187.25 188.5,187.25 184.25,183 176.573,183 174.45,185.123
NetC26_1 on Top Layer "TOP_LAYER_NETC26_1_P192" (solid, pour order 192): 156,195.25 156.75,196 161,196 164,193 164,183.5 162.25,181.75 156.75,181.75 156,182.5
VAC_L on Top Layer "TOP_LAYER_VAC_L_P191" (solid, pour order 191): 50.5,183.75 53,186.25 59.25,186.25 60.5,185 60.438,184.938 60.438,179.002 59.264,177.827 52.585,177.827 50.5,179.912
VAC_N_SW on Top Layer "TOP_LAYER_VAC_N_SW_P190" (solid, pour order 190): 99.25,201.75 101.75,204.25 118.75,204.25 128,195 128,191.25 123.5,186.75 120.25,186.75 114.066,192.934 114.066,195.985 111.676,198.375 100.375,198.375 99.25,199.5
DC_Bus- on Top Layer "TOP_LAYER_DC_BUS-_P180" (solid, pour order 180): 109.814,5.725 129.605,5.725 130.75,4.58 130.75,1.249 129.751,0.25 109.875,0.25 108.5,1.625 108.5,4.411
SN2 on Top Layer "TOP_LAYER_SN2_P166" (solid, pour order 166): 109.985,120.644 117.586,128.245 121.149,128.245 122.904,130 122.75,130.154 122.75,137.989 121.558,139.181 114.534,139.181 112.684,137.331 112.684,130.739 105.25,123.305 105.25,118.612
SN2 on Top Layer "TOP_LAYER_SN2_P162" (solid, pour order 162): 105.25,119.266 108.185,122.202 110.66,122.202 111.089,121.772 111.089,114.477 110.351,113.739 106.028,113.739 105.25,114.517
SN1 on Top Layer "TOP_LAYER_SN1_P164" (solid, pour order 164): 159.912,130.416 160.849,131.354 164.24,131.354 165.104,130.49 165.104,126.393 164.465,125.754 160.81,125.754 159.912,126.652 159.912,129.817
DC_Bus- on Top Layer "TOP_LAYER_DC_BUS-_P163" (solid, pour order 163): 146.838,134.354 147.463,134.979 150.09,134.979 150.529,134.54 150.529,132.018 150.074,131.562 147.478,131.562 146.838,132.202
DC_Bus- on Top Layer "TOP_LAYER_DC_BUS-_P161" (solid, pour order 161): 102.105,119.566 104.359,121.82 104.359,127.323 103.933,127.75 93.153,127.75 91.378,125.974 91.378,120.742 92.553,119.567 92.553,119.566
VCC_12V_SN_U_TIDA-011008_ACDC_Leg1 on Top Layer "TOP_LAYER_VCC_12V_SN_U_TIDA-011008_ACDC_LEG1_P122" (solid, pour order 122): 160.798,122.048 162.25,123.5 167.5,123.5 167.927,123.073 167.927,118.677 167.75,118.5 162.876,118.5 160.798,120.578
VCC_3V3_Wifi on Top Layer "TOP_LAYER_VCC_3V3_WIFI_P151" (solid, pour order 151): 238.61,13.36 242.265,13.36 242.662,12.963 242.662,11.183 242.172,10.693 238.13,10.693 237.834,10.989 237.834,12.584
VCC_12V_SN_U_TIDA-011008_ACDC_Leg2 on Top Layer "TOP_LAYER_VCC_12V_SN_U_TIDA-011008_ACDC_LEG2_P127" (solid, pour order 127): 106.722,110.071 108.155,111.504 113.405,111.504 113.832,111.077 113.832,106.681 113.655,106.504 108.787,106.504 106.722,108.57
NetD13_U_TIDA-011008_ACDC_Leg2_2 on Top Layer "TOP_LAYER_NETD13_U_TIDA-011008_ACDC_LEG2_2_P126" (solid, pour order 126): 100.299,111.353 100.336,111.39 103.518,111.39 104.583,110.326 104.583,108.386 103.339,107.143 99.851,107.143 99.848,107.146 99.848,111.353
VCC_12V on Top Layer "TOP_LAYER_VCC_12V_P125" (solid, pour order 125): 93.409,108.859 93.409,110.326 94.711,111.628 98.357,111.628 98.5,111.485 98.5,106.821 98.25,106.571 93.75,106.571 93.409,106.911
VCC_12V on Top Layer "TOP_LAYER_VCC_12V_P124" (solid, pour order 124): 148.276,123.5 152.717,123.5 152.901,123.316 152.901,119.126 152.65,118.875 148.727,118.875 147.816,119.786 147.816,123.04
NetD13_U_TIDA-011008_ACDC_Leg1_2 on Top Layer "TOP_LAYER_NETD13_U_TIDA-011008_ACDC_LEG1_2_P123" (solid, pour order 123): 154.623,123.418 157.35,123.418 158.65,122.119 158.65,120.705 157.243,119.299 154.894,119.299 154.894,119.324 154.518,119.699 154.518,123.314
VCC_5V on Top Layer "TOP_LAYER_VCC_5V_P121" (solid, pour order 121): 83.883,83.843 84.592,84.552 86.408,84.552 86.408,85.368 87.161,86.12 83.621,86.12 83.358,85.857 83.358,84.018 83.533,83.843
VCC_5V on Top Layer "TOP_LAYER_VCC_5V_P119" (solid, pour order 119): 89.775,81.631 91.927,81.631 92.26,81.298 92.26,77.214 91.789,76.743 90.804,76.743 90.375,77.171 90.375,80.432 89.761,81.047 89.761,81.182
VCC_12V on Top Layer "TOP_LAYER_VCC_12V_P115" (solid, pour order 115): 83.945,80.089 83.953,80.096 85.226,80.096 86.083,80.953 86.295,80.953 86.307,80.942 86.307,76.88 86.17,76.743 84.645,76.743 83.9,77.488 83.9,80.021
NetC70_1 on Top Layer "TOP_LAYER_NETC70_1_P118" (solid, pour order 118): 18 vertices, not listed, extent 86.511,79.218 88.8,81.107
NetC70_1 on Top Layer "TOP_LAYER_NETC70_1_P117" (solid, pour order 117): 87.908,80.89 89.177,80.89 89.601,80.467 89.601,77.49 89.425,77.314 88.578,77.314 88.578,79.499 88.071,80.006 87.755,80.006 87.755,80.283 87.846,80.373 87.846,80.829
NetC70_2 on Top Layer "TOP_LAYER_NETC70_2_P116" (solid, pour order 116): 87.019,82.486 87.373,82.84 88.995,82.84 89.17,82.665 89.17,82.05 89.069,81.948 87.074,81.948 87.019,82.004 87.019,82.164
VCC_5V on Top Layer "TOP_LAYER_VCC_5V_P113" (solid, pour order 113): 81.055,70.351 81.746,70.351 82.171,70.777 83.595,70.777 83.808,70.99 83.808,71.446 83.496,71.757 82.866,71.757 82.501,72.122 82.501,73.353 82.068,73.786 80.677,73.786 80.313,73.421 80.313,71.094
VCC_3V3 on Top Layer "TOP_LAYER_VCC_3V3_P112" (solid, pour order 112): 85.622,70.351 88.578,70.351 88.775,70.548 88.775,72.051 88.167,72.658 85.823,72.658 85.383,72.218 85.383,70.59
NetC26_1 on Top Layer "TOP_LAYER_NETC26_1_P076" (solid, pour order 76): 167.973,163.737 183.487,163.737 186.9,167.15 187,167.25 193,167.25 193.5,166.75 193.5,164.835 186.665,158 167.973,158
AC_N on Top Layer "TOP_LAYER_AC_N_P094" (solid, pour order 94): 4.7,167.2 15.05,167.2 23.75,158.5 23.75,154.94 22.31,153.5 5.391,153.5 2.719,156.172 2.719,165.219
NetF1_1 on Top Layer "TOP_LAYER_NETF1_1_P087" (solid, pour order 87): 19.25,177 29,177 30,176 30,172.739 28.669,171.408 19.842,171.408 18.75,172.5 18.75,176.5
NetL2_4 on Top Layer "TOP_LAYER_NETL2_4_P084" (solid, pour order 84): 42.955,160.795 60.205,160.795 62.5,158.5 62.5,155.25 64.059,153.691 69.997,153.691 71.75,155.445 71.75,162.25 64.5,169.5 42,169.5 40.25,167.75 40.25,163.5
VAC_N on Top Layer "TOP_LAYER_VAC_N_P083" (solid, pour order 83): 97.5,186.75 103.079,186.75 103.909,185.92 103.909,182.409 98.25,176.75 64.25,176.75 63.25,177.75 63.25,184.75 65.25,186.75 71.5,186.75 77.75,180.5 91.25,180.5
VAC_L_Relay on Top Layer "TOP_LAYER_VAC_L_RELAY_P064" (solid, pour order 64): 92.25,159.964 93.5,158.714 93.5,155.737 90.228,152.464 85.587,152.464 84.863,153.188 84.863,158.289 86.538,159.964
NetR18_1 on Top Layer "TOP_LAYER_NETR18_1_P078" (solid, pour order 78): 195.165,176.05 200.165,176.05 200.165,173.8 195.165,173.8
NetR14_1 on Top Layer "TOP_LAYER_NETR14_1_P077" (solid, pour order 77): 200.165,181.25 200.165,178.95 195.165,178.95 195.165,181.25
NetC24_1 on Top Layer "TOP_LAYER_NETC24_1_P073" (solid, pour order 73): 148.25,188.645 148.25,181.5 149,180.75 152.75,180.75 153.734,179.766 153.734,176.919 152.815,176 135.626,176
VAC_L_Relay on Top Layer "TOP_LAYER_VAC_L_RELAY_P068" (solid, pour order 68): 89.867,159.736 102.75,172.5 102.75,179.858 105.75,182.858 108.142,185.25 112,185.25 112.684,184.566 112.684,183.934 111.5,182.75 110.024,182.75 107.25,179.976 107.25,171.11 93.061,156.921 92.252,156.921 89.867,159.306
VAC_N_Relay on Top Layer "TOP_LAYER_VAC_N_RELAY_P066" (solid, pour order 66): 98.533,196.5 110.75,196.5 112.25,195 112.25,190.592 110.25,188.592 97.408,188.592 95.75,190.25 95.75,193.717
NetC24_1 on Top Layer "TOP_LAYER_NETC24_1_P062" (solid, pour order 62): 119.741,175.866 139.875,196 146.5,196 148.25,194.25 148.25,188.521 126.229,166.5 119.741,166.5
VAC_L_SW on Top Layer "TOP_LAYER_VAC_L_SW_P057" (solid, pour order 57): 17 vertices, not listed, extent 96.5,137.975 106.68,156.692
NetC25_2 on Top Layer "TOP_LAYER_NETC25_2_P051" (solid, pour order 51): 156.187,174.5 160.437,178.75 182.25,178.75 183.5,177.5 183.5,169.25 181.828,167.578 168.672,167.578 141.422,167.578 138.75,170.25 138.75,173.5 139.75,174.5
NetC26_1 on Top Layer "TOP_LAYER_NETC26_1_P049" (solid, pour order 49): 140.75,163 149.565,163 152.565,166 165.987,166 168.25,163.737 168.25,158 164.5,154.25 141.25,154.25 140,155.5 140,162.25
PV_Input+ on Top Layer "TOP_LAYER_PV_INPUT+_P013" (solid, pour order 13): 11.5,20.75 15.25,17 15.25,8.5 18.25,5.5 30.8,5.5 32.241,6.941 32.241,10.121 31.162,11.2 21.3,11.2 18.25,14.25 18.25,20 19,20.75
PV_Input+ on Top Layer "TOP_LAYER_PV_INPUT+_P004" (solid, pour order 4): 9,28.5 26,28.5 28.25,26.25 35.75,26.25 36.5,25.5 36.5,17 36.25,16.75 27.25,16.75 23.5,20.5 9.25,20.5 9,20.75
PV_Input- on Top Layer "TOP_LAYER_PV_INPUT-_P000" (solid, pour order 0): 9,30.25 26.25,30.25 28.5,28 35.5,28 36.5,29 36.5,38.5 35,40 9,40
DC_Bus- on Bottom Layer "BOTTOM_LAYER_DC_BUS-_P256" (solid, remove dead copper, pour order 256): 77 vertices, not listed, extent 1,41.201 174.046,146.75
DC_Bus- on Bottom Layer "BOTTOM_LAYER_DC_BUS-_P188" (solid, pour order 188): 23.413,146.42 28.872,151.879 28.872,161.383 32.75,165.26 32.75,181.376 36.124,184.75 40.06,184.75 41.06,183.75 41.043,183.733 41.043,179.247 39.623,177.827 39.623,162.105 42.294,159.433 42.294,149.839 45.594,146.54
SN_U_TIDA-011008_ACDC_Leg1 on Bottom Layer "BOTTOM_LAYER_SN_U_TIDA-011008_ACDC_LEG1_P172" (solid, remove dead copper, pour order 172): 166.042,130.195 167.011,131.163 173.833,131.163 176.166,128.831 176.166,113.901 175.922,113.657 168.072,113.657 166.042,115.687
SN_U_TIDA-011008_ACDC_Leg2 on Bottom Layer "BOTTOM_LAYER_SN_U_TIDA-011008_ACDC_LEG2_P170" (solid, remove dead copper, pour order 170): 112.171,119.31 119.72,119.31 122.75,116.28 122.75,104.007 120.55,101.807 113.82,101.807 111.798,103.829 111.798,118.937
GND_WiFi on Bottom Layer "BOTTOM_LAYER_GND_WIFI_P155" (solid, remove dead copper, pour order 155): 207.121,29.975 208.646,31.5 250.25,31.5 251.25,30.5 251.5,30.5 251.5,1.75 250.25,0.5 208.409,0.5 207.192,1.717 207.192,29.905
NetC12_1 on Bottom Layer "BOTTOM_LAYER_NETC12_1_P023" (solid, pour order 23): 51.75,28.5 85.85,28.5 91.618,34.268 91.618,49.248 91.33,49.536 88.041,49.536 85.402,46.897 53.892,46.897 50.083,43.088 50.083,30.167
DC_Bus+ on Bottom Layer "Bottom Layer-DC_Bus+" (solid, pour order 262): 40 vertices, not listed, extent 106.275,2.5 203,142
GND_WiFi on Bottom Layer "BOTTOM_LAYER_GND_WIFI_P232" (solid, pour order 232): 34.493,65.814 16.698,65.814 9.73,72.781 9.73,77.357 1.738,77.357 1,78.095 1,52.363 2.113,51.25 43.222,51.25 46.027,54.055 46.027,60.683
GND_WiFi on Bottom Layer "BOTTOM_LAYER_GND_WIFI_P231" (solid, pour order 231): 45.447,60.164 46.076,60.793 46.076,76.108 45.194,76.99 39.545,76.99 38.18,75.625 38.18,66.667 37.327,65.814 34.493,65.814 34.137,65.458 34.137,62.256 36.228,60.164
DC_Bus- on Bottom Layer "BOTTOM_LAYER_DC_BUS-_P249" (solid, pour order 249): 111.473,40.24 121.248,40.24 122.208,41.201 122.208,45.94 122.834,46.566 127.233,46.566 129.221,44.578 129.221,41.691 126.336,38.805 111.944,38.805 111.473,39.276
NetC8_2 on Bottom Layer "BOTTOM_LAYER_NETC8_2_P241" (solid, pour order 241): 18 vertices, not listed, extent 52.994,0.25 91.421,25.261
GND_WiFi on Bottom Layer "BOTTOM_LAYER_GND_WIFI_P230" (solid, pour order 230): 8.873,76.5 9.73,77.357 9.73,83.082 11,84.352 11,85.693 10.115,86.579 1.379,86.579 1,86.2 1,78.095 2.595,76.5 5.96,76.5
VCC_3V3_Wifi on Bottom Layer "BOTTOM_LAYER_VCC_3V3_WIFI_P227" (solid, pour order 227): 34.528,65.133 38.202,65.133 39.09,64.245 43.59,64.245 43.899,63.936 43.899,63.514 43.873,63.514 43.373,63.014 38.84,63.014 37.709,61.883 34.509,61.883
GND_WiFi on Bottom Layer "BOTTOM_LAYER_GND_WIFI_P224" (solid, pour order 224): 38.98,73.359 41.421,73.359 42.737,74.675 44.613,74.675 45.039,75.101 45.039,76.434 44.483,76.99 39.915,76.99 38.98,76.055
VAC_L_Relay on Bottom Layer "BOTTOM_LAYER_VAC_L_RELAY_P203" (solid, pour order 203): 89.867,159.736 102.75,172.5 102.75,179.858 105.75,182.858 108.142,185.25 112,185.25 112.684,184.566 112.684,183.934 111.5,182.75 110.024,182.75 107.25,179.976 107.25,171.11 93.061,156.921 92.252,156.921 89.867,159.306
SN2 on Bottom Layer "BOTTOM_LAYER_SN2_P047" (solid, pour order 47): 17 vertices, not listed, extent 105.25,109.035 122.75,139.181
AC_L on Bottom Layer "BOTTOM_LAYER_AC_L_P098" (solid, pour order 98): 7.276,171.739 15,171.739 17,173.739 17,177.975 19.25,180.225 23.591,180.225 24.828,181.463 24.828,185.822 23.75,186.9 6.15,186.9 3.212,183.962 3.212,175.803
DC_Bus- on Bottom Layer "BOTTOM_LAYER_DC_BUS-_P216" (solid, pour order 216): 95.074,49.481 102.233,49.481 107.223,44.491 107.223,39.458 106.015,38.25 96.245,38.25 95.005,39.489 95.005,49.407 95.074,49.477
VCC_3V3_Wifi on Bottom Layer "BOTTOM_LAYER_VCC_3V3_WIFI_P150" (solid, pour order 150): 24 vertices, not listed, extent 213.361,1.159 242.662,13.36
NetC24_1 on Bottom Layer "BOTTOM_LAYER_NETC24_1_P205" (solid, pour order 205): 101,137.269 104.28,137.269 107.25,140.239 107.25,168.25 115.25,176.25 120.125,176.25 121.25,175.125 121.25,168 119.75,166.5 115.091,166.5 113.591,165 113.591,139.814 106.7,132.923 101,132.923
NetF2_1 on Bottom Layer "BOTTOM_LAYER_NETF2_1_P090" (solid, pour order 90): 20.375,169.5 29.45,169.5 30.25,168.7 30.25,164.5 29.75,164 19.907,164 19,164.907 19,168.125
NetD1_3 on Bottom Layer "BOTTOM_LAYER_NETD1_3_P034" (solid, pour order 34): 19 vertices, not listed, extent 97.317,22.5 127.303,35.805
DC_Bus- on Bottom Layer "BOTTOM_LAYER_DC_BUS-_P213" (solid, pour order 213): 122.834,46.566 126.226,46.566 126.65,46.142 126.65,42.196 126.083,41.628 122.701,41.628 122.208,42.122 122.208,45.94 122.208,42.122 122.208,45.94
NetC26_1 on Bottom Layer "BOTTOM_LAYER_NETC26_1_P210" (solid, pour order 210): 156,195.25 156.75,196 161,196 164,193 164,183.5 162.25,181.75 156.75,181.75 156,182.5
NetC25_2 on Bottom Layer "BOTTOM_LAYER_NETC25_2_P208" (solid, pour order 208): 174.45,186.2 183.5,195.25 187.75,195.25 189.75,193.25 192,193.25 193.99,191.26 193.99,187.99 193.25,187.25 188.5,187.25 184.25,183 176.573,183 174.45,185.123
VAC_L on Bottom Layer "BOTTOM_LAYER_VAC_L_P206" (solid, pour order 206): 53,186.25 59.25,186.25 61.75,183.75 61.75,177.691 65.691,173.75 75.5,173.75 83.478,165.771 83.478,155.315 82.164,154 78.5,154 70.5,162 50.5,182 50.5,183.75
VAC_L_SW on Bottom Layer "BOTTOM_LAYER_VAC_L_SW_P204" (solid, pour order 204): 17 vertices, not listed, extent 96.5,137.975 106.68,156.692
VAC_L_Relay on Bottom Layer "BOTTOM_LAYER_VAC_L_RELAY_P202" (solid, pour order 202): 92.25,159.964 93.5,158.714 93.5,155.737 90.228,152.464 85.587,152.464 84.863,153.188 84.863,158.289 86.538,159.964
VAC_N_Relay on Bottom Layer "BOTTOM_LAYER_VAC_N_RELAY_P201" (solid, pour order 201): 98.533,196.5 110.75,196.5 112.25,195 112.25,190.592 110.25,188.592 97.408,188.592 95.75,190.25 95.75,193.717
VAC_N on Bottom Layer "BOTTOM_LAYER_VAC_N_P200" (solid, pour order 200): 97.5,186.75 100.985,186.75 101.5,186.235 101.5,180 98.25,176.75 64.25,176.75 63.25,177.75 63.25,184.75 65.25,186.75 71.5,186.75 77.75,180.5 91.25,180.5
DC_Bus- on Bottom Layer "BOTTOM_LAYER_DC_BUS-_P181" (solid, pour order 181): 110.337,6.247 129.083,6.247 130.75,4.58 130.75,1.249 129.751,0.25 109.875,0.25 108.5,1.625 108.5,4.411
